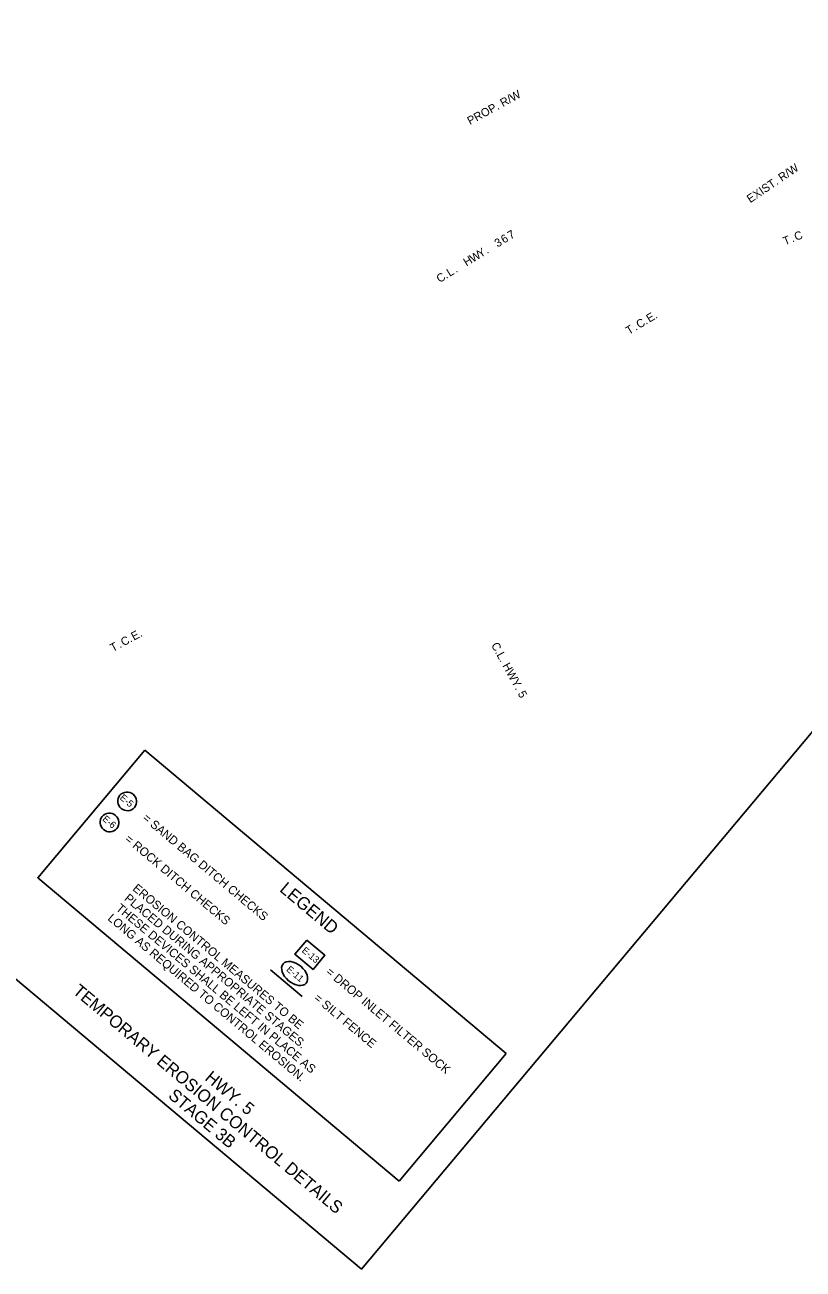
# Model space of a CAD drawing. Extents: x 1292584 to 1294692, y 222754 to 224578.
# Drawn here: x 1293562 to 1294127, y 222754 to 223658 of the extents above; entities that cross this region are included whole.
import ezdxf

# ---------------------------------------------------------------- set-up
doc = ezdxf.new("R2010")
doc.units = 0
for name, color, linetype in [('1', 7, 'Continuous'), ('R_Striping', 7, 'Continuous'), ('S_CROSS_DRAIN_ANNOT', 7, 'Continuous'), ('S_FIBER_OPTIC_CABLE_ANNOT', 7, 'Continuous'), ('S_GUARDRAIL', 7, 'Continuous'), ('S_MISC_TOPO_POINT', 7, 'Continuous'), ('S_SURVEY_TEXT_ANNOT', 7, 'Continuous')]:
    doc.layers.add(name, color=color, linetype=linetype)

msp = doc.modelspace()

# ---------------------------------------------------------------- linework, layer by layer
at = {"layer": '1'}
msp.add_lwpolyline([(1292584.05, 223779.83), (1293254.04, 224578.3), (1294171.77, 223808.23), (1294139.92, 223770.28), (1294291.79, 223642.84), (1294281.83, 223630.97), (1294336.68, 223584.95), (1294241.87, 223471.95), (1294339.54, 223390), (1293806.17, 222754.35)], close=True, dxfattribs=at)
msp.add_lwpolyline([(1292584.05, 223779.83), (1293254.04, 224578.3), (1294171.77, 223808.23), (1294139.92, 223770.28), (1294291.79, 223642.84), (1294281.83, 223630.97), (1294336.68, 223584.95), (1294241.87, 223471.95), (1294339.54, 223390), (1293806.17, 222754.35)], close=True, dxfattribs=at)
msp.add_lwpolyline([(1292584.05, 223779.83), (1293254.04, 224578.3), (1294171.77, 223808.23), (1294139.92, 223770.28), (1294291.79, 223642.84), (1294281.83, 223630.97), (1294336.68, 223584.95), (1294241.87, 223471.95), (1294339.54, 223390), (1293806.17, 222754.35)], close=True, dxfattribs=at)
msp.add_lwpolyline([(1292584.05, 223779.83), (1293254.04, 224578.3), (1294171.77, 223808.23), (1294139.92, 223770.28), (1294291.79, 223642.84), (1294281.83, 223630.97), (1294336.68, 223584.95), (1294241.87, 223471.95), (1294339.54, 223390), (1293806.17, 222754.35)], close=True, dxfattribs=at)
msp.add_lwpolyline([(1292584.05, 223779.83), (1293254.04, 224578.3), (1294171.77, 223808.23), (1294139.92, 223770.28), (1294291.79, 223642.84), (1294281.83, 223630.97), (1294336.68, 223584.95), (1294241.87, 223471.95), (1294339.54, 223390), (1293806.17, 222754.35)], close=True, dxfattribs=at)
msp.add_lwpolyline([(1292584.05, 223779.83), (1293254.04, 224578.3), (1294171.77, 223808.23), (1294139.92, 223770.28), (1294291.79, 223642.84), (1294281.83, 223630.97), (1294336.68, 223584.95), (1294241.87, 223471.95), (1294339.54, 223390), (1293806.17, 222754.35)], close=True, dxfattribs=at)
at = {"layer": 'S_CROSS_DRAIN_ANNOT'}
for p, q in [((1293911.34, 222911.05), (1293648.85, 223131.31)), ((1293833.53, 222818.32), (1293911.34, 222911.05))]:
    msp.add_line(p, q, dxfattribs=at)
msp.add_lwpolyline([(1293648.85, 223131.31), (1293571.04, 223038.57), (1293833.53, 222818.32)], dxfattribs=at)
at = {"layer": 'S_GUARDRAIL'}
msp.add_lwpolyline([(1293740.1, 222971.59), (1293763.18, 222952.23)], dxfattribs=at)
at = {"layer": 'S_SURVEY_TEXT_ANNOT'}
msp.add_lwpolyline([(1293766.52, 222993.26), (1293779.63, 222982.25), (1293771.01, 222971.97), (1293757.89, 222982.98)], close=True, dxfattribs=at)
for centre, major_axis, ratio in [((1293635.98, 223094.03), (-5.27, 4.42), 0.97521), ((1293623.13, 223078.71), (-5.27, 4.42), 0.97521), ((1293757.64, 222969.05), (8.39, -7.04), 0.622952)]:
    msp.add_ellipse(centre, major_axis=major_axis, ratio=ratio, dxfattribs=at)

# ---------------------------------------------------------------- texts
at = {"layer": 'R_Striping'}
for s, rotation, p in [('7', 31.13376, (1293914.49, 223501.89)), ('C', 21.6622, (1294121.89, 223501)), ('3', 31.24435, (1293905.05, 223496.17)), ('6', 31.19047, (1293909.65, 223498.96)), ('T', 21.6622, (1294113.72, 223497.75)), ('.', 21.6622, (1294119.17, 223499.91)), ('H', 31.49372, (1293882.45, 223482.37)), ('W', 31.45559, (1293887.04, 223485.18)), ('Y', 31.39132, (1293892.51, 223488.53)), ('.', 31.33367, (1293897.43, 223491.53)), ('L', 31.49372, (1293870.24, 223474.89)), ('C', 31.49372, (1293862.91, 223470.4)), ('.', 31.49372, (1293867.74, 223473.36)), ('.', 31.49372, (1293874.83, 223477.71)), ('C', 30.9348, (1294007.92, 223437.19)), ('E', 30.9348, (1294015.29, 223441.61)), ('.', 30.9348, (1294019.91, 223444.38)), ('T', 30.9348, (1294000.38, 223432.68)), ('.', 30.9348, (1294005.41, 223435.69)), ('.', 30.9348, (1294012.78, 223440.11)), ('E', 28.53219, (1293640.87, 223210.68)), ('T', 28.53219, (1293625.59, 223202.37)), ('C', 28.53219, (1293633.32, 223206.57)), ('.', 28.53219, (1293638.3, 223209.28)), ('.', 28.53219, (1293645.6, 223213.25)), ('C.L. HWY. 5', 298.77322, (1293900.19, 223207.5)), ('.', 28.53219, (1293630.74, 223205.17))]:
    msp.add_text(s, height=6, rotation=rotation, dxfattribs=at).set_placement(p)
at = {"layer": 'S_FIBER_OPTIC_CABLE_ANNOT'}
for s, rotation, p in [('PROP. R/W', 28.60191, (1293885.01, 223585.14)), ('EXIST. R/W', 34.11752, (1294088.57, 223528.38))]:
    msp.add_text(s, height=6, rotation=rotation, dxfattribs=at).set_placement(p)
at = {"layer": 'S_GUARDRAIL'}
msp.add_text('LEGEND', height=9.143, rotation=320.00011, dxfattribs=at).set_placement((1293746.11, 223029.2))
at = {"layer": 'S_MISC_TOPO_POINT'}
for s, p in [('TEMPORARY EROSION CONTROL DETAILS', (1293595.79, 222955.14)), ('HWY. 5', (1293691.82, 222892.19)), ('STAGE 3B', (1293665.21, 222879.27))]:
    msp.add_text(s, height=9, rotation=320, dxfattribs=at).set_placement(p)
at = {"layer": 'S_SURVEY_TEXT_ANNOT'}
for s, height, p in [('E-5 ', 4.876, (1293630.24, 223095.96)), ('E-6 ', 4.876, (1293617.6, 223080.57)), ('= SAND BAG DITCH CHECKS', 6.25, (1293646.63, 223081.01)), ('= ROCK DITCH CHECKS', 6.25, (1293633.78, 223065.69)), ('EROSION CONTROL MEASURES TO BE', 6.25, (1293639.47, 223029.94)), ('THESE DEVICES SHALL BE LEFT IN PLACE AS ', 6.25, (1293627.37, 223015.52)), ('PLACED DURING APPROPRIATE STAGES. ', 6.25, (1293633.42, 223022.73)), ('LONG AS REQUIRED TO CONTROL EROSION.', 6.25, (1293621.32, 223008.31)), ('E-13', 4.876, (1293762.43, 222985.03)), ('E-11 ', 4.876, (1293751.2, 222971.33)), ('= DROP INLET FILTER SOCK', 6.25, (1293779.79, 222969.28)), ('= SILT FENCE', 6.25, (1293771.11, 222950.21))]:
    msp.add_text(s, height=height, rotation=320.00011, dxfattribs=at).set_placement(p)

doc.saveas('drawing.dxf')
